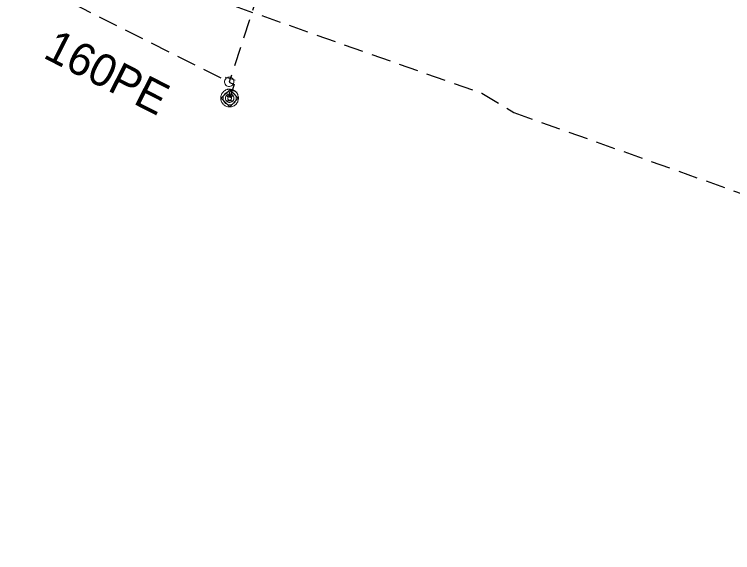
# Model space of a CAD drawing. Extents: x -735085 to -733500, y -1044153 to -1043402.
# Drawn here: x -734928.23 to -734892.74, y -1043550.56 to -1043523.99 of the extents above; entities that cross this region are included whole.
import ezdxf

# ---------------------------------------------------------------- set-up
doc = ezdxf.new("R2010")
doc.units = 0
doc.header["$LTSCALE"] = 0.32
doc.linetypes.add('MEDIUM_DASHED', pattern=[4.5, 3, -1.5])
doc.layers.add('15', color=7, linetype='Continuous')
doc.layers.add('8', color=7, linetype='Continuous', lineweight=13)

msp = doc.modelspace()

# ---------------------------------------------------------------- linework, layer by layer
at = {"layer": '8', "linetype": 'MEDIUM_DASHED', "lineweight": 25}
for p, q in [((-734912.138, -1043510.559), (-734917.559, -1043527.16)), ((-734926.609, -1043522.81), (-734917.614, -1043527.33)), ((-734917.559, -1043527.16), (-734917.614, -1043527.33))]:
    msp.add_line(p, q, dxfattribs=at)
at = {"layer": '8'}
for p, q in [((-734917.806, -1043527.079), (-734917.315, -1043527.239)), ((-734917.706, -1043527.657), (-734917.215, -1043527.821)), ((-734917.754, -1043527.975), (-734917.678, -1043528.058)), ((-734917.706, -1043527.903), (-734917.634, -1043528.024)), ((-734917.592, -1043527.845), (-734917.592, -1043528.014)), ((-734917.546, -1043528.022), (-734917.475, -1043527.915)), ((-734917.506, -1043528.051), (-734917.442, -1043527.993)), ((-734917.711, -1043528.248), (-734917.476, -1043528.248))]:
    msp.add_line(p, q, dxfattribs=at)
at = {"layer": '8', "linetype": 'MEDIUM_DASHED', "lineweight": 25}
for points in [[(-734928.23, -1043519.739), (-734905.133, -1043527.879), (-734903.548, -1043528.837), (-734842.335, -1043550.559)], [(-734917.614, -1043527.33), (-734917.364, -1043527.455), (-734917.46, -1043527.74), (-734917.59, -1043528.13)]]:
    msp.add_lwpolyline(points, dxfattribs=at)
at = {"layer": '8'}
for points in [[(-734917.382, -1043527.318), (-734917.389, -1043527.266), (-734917.406, -1043527.216), (-734917.434, -1043527.172), (-734917.473, -1043527.135), (-734917.517, -1043527.108), (-734917.568, -1043527.092), (-734917.62, -1043527.087), (-734917.671, -1043527.094), (-734917.72, -1043527.113), (-734917.764, -1043527.143), (-734917.799, -1043527.182), (-734917.826, -1043527.227), (-734917.84, -1043527.278), (-734917.843, -1043527.33), (-734917.835, -1043527.382), (-734917.815, -1043527.43), (-734917.784, -1043527.473), (-734917.745, -1043527.508), (-734917.698, -1043527.532), (-734917.647, -1043527.546), (-734917.595, -1043527.548), (-734917.544, -1043527.538), (-734917.495, -1043527.516), (-734917.453, -1043527.484), (-734917.421, -1043527.444), (-734917.397, -1043527.397), (-734917.384, -1043527.346)], [(-734917.272, -1043528.126), (-734917.278, -1043528.065), (-734917.296, -1043528.005), (-734917.325, -1043527.95), (-734917.364, -1043527.902), (-734917.411, -1043527.862), (-734917.465, -1043527.832), (-734917.524, -1043527.812), (-734917.586, -1043527.805), (-734917.648, -1043527.809), (-734917.708, -1043527.825), (-734917.763, -1043527.853), (-734917.813, -1043527.89), (-734917.854, -1043527.937), (-734917.886, -1043527.99), (-734917.906, -1043528.049), (-734917.916, -1043528.11), (-734917.913, -1043528.172), (-734917.898, -1043528.232), (-734917.872, -1043528.289), (-734917.836, -1043528.339), (-734917.79, -1043528.382), (-734917.738, -1043528.414), (-734917.68, -1043528.437), (-734917.619, -1043528.447), (-734917.557, -1043528.446), (-734917.496, -1043528.433), (-734917.439, -1043528.408), (-734917.388, -1043528.373), (-734917.344, -1043528.329), (-734917.31, -1043528.277), (-734917.286, -1043528.22), (-734917.274, -1043528.159)], [(-734917.386, -1043528.126), (-734917.392, -1043528.077), (-734917.409, -1043528.03), (-734917.437, -1043527.989), (-734917.475, -1043527.956), (-734917.519, -1043527.932), (-734917.567, -1043527.92), (-734917.617, -1043527.919), (-734917.665, -1043527.931), (-734917.71, -1043527.953), (-734917.748, -1043527.986), (-734917.777, -1043528.026), (-734917.796, -1043528.073), (-734917.803, -1043528.122), (-734917.798, -1043528.172), (-734917.781, -1043528.219), (-734917.754, -1043528.261), (-734917.717, -1043528.295), (-734917.674, -1043528.319), (-734917.626, -1043528.333), (-734917.576, -1043528.334), (-734917.527, -1043528.324), (-734917.482, -1043528.302), (-734917.443, -1043528.27), (-734917.413, -1043528.231), (-734917.394, -1043528.185), (-734917.386, -1043528.135)], [(-734917.493, -1043528.129), (-734917.499, -1043528.096), (-734917.516, -1043528.067), (-734917.542, -1043528.046), (-734917.574, -1043528.035), (-734917.608, -1043528.036), (-734917.639, -1043528.048), (-734917.664, -1043528.071), (-734917.68, -1043528.1), (-734917.684, -1043528.134), (-734917.677, -1043528.167), (-734917.658, -1043528.195), (-734917.631, -1043528.215), (-734917.599, -1043528.225), (-734917.565, -1043528.222), (-734917.534, -1043528.208), (-734917.51, -1043528.185), (-734917.496, -1043528.154)]]:
    msp.add_lwpolyline(points, close=True, dxfattribs=at)
for points in [[(-734917.159, -1043528.118), (-734917.161, -1043528.073), (-734917.168, -1043528.028), (-734917.18, -1043527.983), (-734917.196, -1043527.941), (-734917.217, -1043527.9), (-734917.242, -1043527.861), (-734917.271, -1043527.826), (-734917.303, -1043527.793), (-734917.339, -1043527.765), (-734917.377, -1043527.74), (-734917.418, -1043527.719), (-734917.461, -1043527.702), (-734917.505, -1043527.69), (-734917.55, -1043527.683), (-734917.596, -1043527.681), (-734917.642, -1043527.683), (-734917.687, -1043527.69), (-734917.731, -1043527.702), (-734917.774, -1043527.719), (-734917.815, -1043527.74), (-734917.853, -1043527.765), (-734917.889, -1043527.793), (-734917.921, -1043527.826), (-734917.95, -1043527.861), (-734917.975, -1043527.9), (-734917.996, -1043527.941), (-734918.012, -1043527.983), (-734918.024, -1043528.028), (-734918.031, -1043528.073), (-734918.034, -1043528.119), (-734918.031, -1043528.164), (-734918.024, -1043528.209), (-734918.012, -1043528.254), (-734917.996, -1043528.296), (-734917.975, -1043528.337), (-734917.95, -1043528.376), (-734917.921, -1043528.411), (-734917.889, -1043528.444), (-734917.853, -1043528.472), (-734917.815, -1043528.497), (-734917.774, -1043528.518), (-734917.731, -1043528.535), (-734917.687, -1043528.546), (-734917.642, -1043528.554), (-734917.596, -1043528.556), (-734917.55, -1043528.554), (-734917.505, -1043528.546), (-734917.461, -1043528.535), (-734917.418, -1043528.518), (-734917.377, -1043528.497), (-734917.339, -1043528.472), (-734917.303, -1043528.444), (-734917.271, -1043528.411), (-734917.242, -1043528.376), (-734917.217, -1043528.337), (-734917.196, -1043528.296), (-734917.18, -1043528.254), (-734917.168, -1043528.209), (-734917.161, -1043528.164), (-734917.159, -1043528.119)], [(-734918.009, -1043528.125), (-734917.588, -1043527.704), (-734917.166, -1043528.127), (-734917.587, -1043528.55), (-734918.008, -1043528.125)]]:
    msp.add_lwpolyline(points, dxfattribs=at)

# ---------------------------------------------------------------- texts
at = {"layer": '15'}
msp.add_text('160PE ', height=1.6, rotation=333, dxfattribs=at).set_placement((-734926.865, -1043526.096))

doc.saveas('drawing.dxf')
